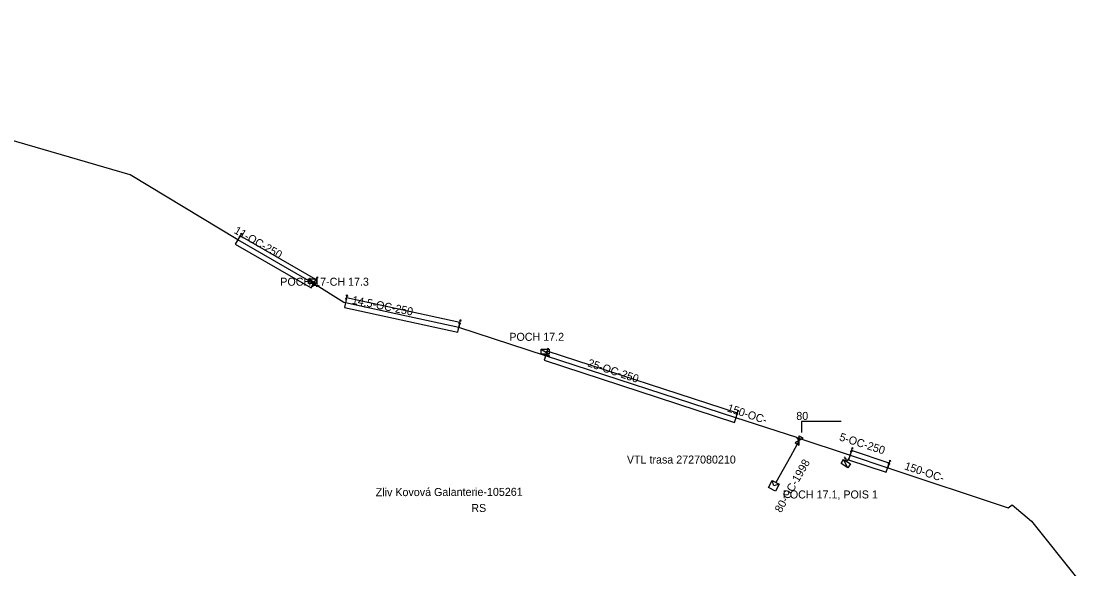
# Model space of a CAD drawing. Extents: x -762500 to -761250, y -1154668 to -1154000.
# Drawn here: x -761875 to -761743, y -1154354.6 to -1154286.2 of the extents above; entities that cross this region are included whole.
import ezdxf

# ---------------------------------------------------------------- set-up
doc = ezdxf.new("R2010")
doc.units = 0
for name, color, linetype in [('Vrstva 1', 7, 'Continuous'), ('Vrstva 13', 7, 'Continuous'), ('Vrstva 16', 7, 'Continuous'), ('Vrstva 19', 7, 'Continuous'), ('Vrstva 2', 7, 'Continuous'), ('Vrstva 20', 7, 'Continuous'), ('Vrstva 60', 7, 'Continuous'), ('Vrstva 8', 7, 'Continuous'), ('Vrstva 9', 7, 'Continuous')]:
    doc.layers.add(name, color=color, linetype=linetype)

msp = doc.modelspace()

# ---------------------------------------------------------------- linework, layer by layer
at = {"layer": 'Vrstva 1'}
for points in [[(-761778.07, -1154338.16), (-761785.69, -1154335.72), (-761809.46, -1154327.96), (-761820.31, -1154324.42), (-761826.84, -1154323), (-761834.48, -1154321.34), (-761834.68, -1154321.3), (-761838.48, -1154318.95), (-761847.94, -1154313.5), (-761861.38, -1154305.37), (-761879.88, -1154300), (-761905.56, -1154293.75), (-761932.65, -1154286.17)], [(-761777.78, -1154338.56), (-761778.86, -1154340.53), (-761780.72, -1154343.79)], [(-761778.07, -1154338.16), (-761771.43, -1154340.38), (-761766.71, -1154341.95), (-761751.66, -1154346.95), (-761751.17, -1154346.6), (-761748.75, -1154348.62), (-761742.96, -1154355.87)], [(-761777.78, -1154338.57), (-761778.07, -1154338.16)]]:
    msp.add_lwpolyline(points, dxfattribs=at)
at = {"layer": 'Vrstva 13'}
for points in [[(-761780.279, -1154344.016), (-761780.751, -1154344.897), (-761781.633, -1154344.425), (-761781.16, -1154343.543), (-761780.279, -1154344.016)], [(-761780.279, -1154344.016), (-761780.956, -1154344.22), (-761781.16, -1154343.543)]]:
    msp.add_lwpolyline(points, dxfattribs=at)
at = {"layer": 'Vrstva 19'}
for p, q in [((-761839.11, -1154318.35), (-761838.11, -1154318.95)), ((-761838.61, -1154318.95), (-761838.61, -1154319.35)), ((-761810.02, -1154327.15), (-761809.02, -1154327.75)), ((-761809.52, -1154327.75), (-761809.52, -1154328.15)), ((-761771.714, -1154341.961), (-761772.228, -1154340.914)), ((-761771.808, -1154341.186), (-761771.59, -1154340.85))]:
    msp.add_line(p, q, dxfattribs=at)
for points in [[(-761839.11, -1154318.35), (-761838.11, -1154318.35), (-761838.11, -1154318.95), (-761839.11, -1154318.95), (-761839.11, -1154318.35)], [(-761838.41, -1154318.95), (-761838.41, -1154319.15), (-761838.11, -1154319.15), (-761838.11, -1154319.35)], [(-761810.02, -1154327.15), (-761809.02, -1154327.15), (-761809.02, -1154327.75), (-761810.02, -1154327.75), (-761810.02, -1154327.15)], [(-761809.32, -1154327.75), (-761809.32, -1154327.95), (-761809.02, -1154327.95), (-761809.02, -1154328.15)], [(-761771.714, -1154341.961), (-761772.554, -1154341.417), (-761772.228, -1154340.914), (-761771.388, -1154341.457), (-761771.714, -1154341.961)], [(-761771.976, -1154341.077), (-761771.867, -1154340.909), (-761772.119, -1154340.746), (-761772.01, -1154340.578)]]:
    msp.add_lwpolyline(points, dxfattribs=at)
at = {"layer": 'Vrstva 2'}
for points in [[(-761772.54, -1154336.19), (-761777.49, -1154336.17), (-761777.49, -1154337.57)], [(-761777.269, -1154338.279), (-761778.291, -1154338.84), (-761777.773, -1154339.143), (-761777.787, -1154337.977), (-761777.269, -1154338.279)]]:
    msp.add_lwpolyline(points, dxfattribs=at)
at = {"layer": 'Vrstva 20'}
for points in [[(-761838.48, -1154318.95), (-761838.61, -1154319.35)], [(-761809.46, -1154327.96), (-761809.52, -1154328.15)], [(-761771.43, -1154340.38), (-761771.59, -1154340.85)]]:
    msp.add_lwpolyline(points, dxfattribs=at)
at = {"layer": 'Vrstva 8'}
for p, q in [((-761847.718, -1154313.131), (-761847.94, -1154313.5)), ((-761847.646, -1154313.011), (-761847.425, -1154312.643)), ((-761838.254, -1154318.584), (-761838.48, -1154318.95)), ((-761838.181, -1154318.465), (-761837.955, -1154318.099)), ((-761834.389, -1154320.92), (-761834.48, -1154321.34)), ((-761834.359, -1154320.783), (-761834.268, -1154320.363)), ((-761820.213, -1154324.001), (-761820.31, -1154324.42)), ((-761820.181, -1154323.865), (-761820.083, -1154323.446)), ((-761809.327, -1154327.551), (-761809.46, -1154327.96)), ((-761809.284, -1154327.418), (-761809.15, -1154327.01)), ((-761785.562, -1154335.309), (-761785.69, -1154335.72)), ((-761785.52, -1154335.176), (-761785.392, -1154334.765)), ((-761771.249, -1154339.839), (-761771.113, -1154339.431)), ((-761771.294, -1154339.972), (-761771.43, -1154340.38)), ((-761766.54, -1154341.409), (-761766.404, -1154341.001)), ((-761766.584, -1154341.542), (-761766.72, -1154341.95))]:
    msp.add_line(p, q, dxfattribs=at)
for points in [[(-761847.572, -1154312.752), (-761847.425, -1154312.643), (-761847.452, -1154312.824)], [(-761838.104, -1154318.207), (-761837.955, -1154318.099), (-761837.984, -1154318.281)], [(-761834.372, -1154320.514), (-761834.268, -1154320.363), (-761834.236, -1154320.544)], [(-761820.19, -1154323.596), (-761820.083, -1154323.446), (-761820.054, -1154323.628)], [(-761809.27, -1154327.15), (-761809.15, -1154327.01), (-761809.136, -1154327.193)], [(-761785.51, -1154334.907), (-761785.392, -1154334.765), (-761785.376, -1154334.948)], [(-761771.233, -1154339.57), (-761771.113, -1154339.431), (-761771.1, -1154339.615)], [(-761766.524, -1154341.14), (-761766.404, -1154341.001), (-761766.392, -1154341.185)]]:
    msp.add_lwpolyline(points, dxfattribs=at)
for centre in [(-761847.683, -1154313.071), (-761838.218, -1154318.525), (-761834.374, -1154320.852), (-761820.197, -1154323.933), (-761809.306, -1154327.485), (-761785.541, -1154335.243), (-761771.272, -1154339.905), (-761766.563, -1154341.476)]:
    msp.add_circle(centre, 0.07, dxfattribs=at)
at = {"layer": 'Vrstva 9'}
for points in [[(-761848.24, -1154314.02), (-761838.78, -1154319.47), (-761838.18, -1154318.43), (-761847.64, -1154312.98)], [(-761834.61, -1154321.93), (-761820.44, -1154325.01), (-761820.18, -1154323.83), (-761834.35, -1154320.75)], [(-761809.65, -1154328.53), (-761785.88, -1154336.29), (-761785.5, -1154335.15), (-761809.27, -1154327.39)], [(-761771.62, -1154340.95), (-761766.9, -1154342.52), (-761766.52, -1154341.38), (-761771.24, -1154339.81)]]:
    msp.add_lwpolyline(points, close=True, dxfattribs=at)

# ---------------------------------------------------------------- texts
at = {"layer": 'Vrstva 1'}
for s, rotation, p in [('150-OC-', 341.84365, (-761786.86, -1154334.9)), ('80-OC-1998', 60.27028, (-761780.04, -1154347.65)), ('150-OC-', 341.62895, (-761764.71, -1154342.14))]:
    msp.add_text(s, height=1, rotation=rotation, dxfattribs=at).set_placement(p)
at = {"layer": 'Vrstva 16'}
for s, p in [('Zliv Kovová Galanterie-105261', (-761830.69, -1154345.51)), ('RS', (-761818.75, -1154347.48))]:
    msp.add_text(s, height=1, rotation=0.16101, dxfattribs=at).set_placement(p)
at = {"layer": 'Vrstva 19'}
for s, p in [('POCH 17-CH 17.3', (-761842.62, -1154319.22)), ('POCH 17.2', (-761814, -1154326.1)), ('POCH 17.1, POIS 1', (-761779.84, -1154345.79))]:
    msp.add_text(s, height=1, dxfattribs=at).set_placement(p)
at = {"layer": 'Vrstva 2'}
msp.add_text('80', height=1, dxfattribs=at).set_placement((-761778.14, -1154335.98))
at = {"layer": 'Vrstva 60'}
msp.add_text('VTL trasa 2727080210', height=1, dxfattribs=at).set_placement((-761799.31, -1154341.43))
at = {"layer": 'Vrstva 9'}
for s, rotation, p in [('11-OC-250', 330.25397, (-761848.49, -1154312.6)), ('14,5-OC-250', 348.72138, (-761833.72, -1154321.45)), ('25-OC-250', 341.52454, (-761804.3, -1154329.27)), ('5-OC-250', 342.36196, (-761772.84, -1154338.52))]:
    msp.add_text(s, height=1, rotation=rotation, dxfattribs=at).set_placement(p)

doc.saveas('drawing.dxf')
